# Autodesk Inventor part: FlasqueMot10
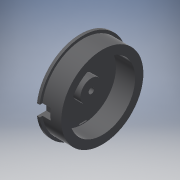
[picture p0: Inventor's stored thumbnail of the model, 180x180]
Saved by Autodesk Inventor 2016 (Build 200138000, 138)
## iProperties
Created: 2013-08
Part Number: FlasqueMot10
Material: Plastique SAN
Document SubType Name: Modeling
Designer: hilarion
Density: 1.068 g/cm^3
Appearance: Rouge
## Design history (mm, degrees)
node "FlasqueMot101"
node "FlasqueMot10"
node "Base1"
